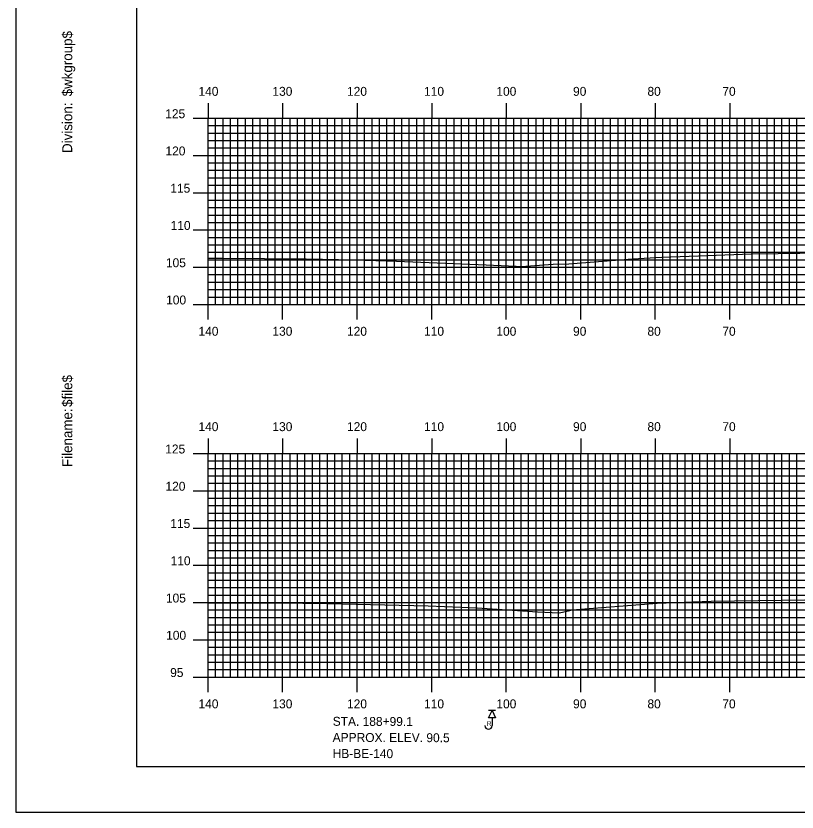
# Model space of a CAD drawing. Extents: x 1788156 to 1788500, y 442591 to 442811.
# Drawn here: x 1788156.3 to 1788261.2, y 442590.5 to 442697.4 of the extents above; entities that cross this region are included whole.
import ezdxf

# ---------------------------------------------------------------- set-up
doc = ezdxf.new("R2010")
doc.units = 0
for name, color, linetype in [('BORDER', 7, 'Continuous'), ('BORING - NO REFUSAL', 7, 'Continuous'), ('BORING - REFUSAL', 7, 'Continuous'), ('H_V ANNOTATION', 7, 'Continuous'), ('MAJOR', 7, 'Continuous'), ('MINOR', 7, 'Continuous'), ('PLOT BOUNDARY', 7, 'Continuous'), ('S_Roadway_Centerline', 7, 'Continuous')]:
    doc.layers.add(name, color=color, linetype=linetype)

msp = doc.modelspace()

# ---------------------------------------------------------------- linework, layer by layer
at = {"layer": 'BORDER'}
msp.add_lwpolyline([(1788172.53, 442596.67), (1788492.53, 442596.67), (1788492.53, 442806.67), (1788172.53, 442806.67)], close=True, dxfattribs=at)
at = {"layer": 'BORING - NO REFUSAL'}
for p, q in [((1788220.71, 442604.17), (1788219.75, 442604.17)), ((1788220.23, 442603.21), (1788220.23, 442602.15))]:
    msp.add_line(p, q, dxfattribs=at)
msp.add_lwpolyline([(1788220.23, 442604.17), (1788220.71, 442603.21), (1788219.75, 442603.21)], close=True, dxfattribs=at)
msp.add_arc((1788219.75, 442602.15), 0.485, 180, 0, dxfattribs=at)
at = {"layer": 'MAJOR'}
for p, q in [((1788182.13, 442685.67), (1788182.13, 442683.67)), ((1788192.13, 442685.67), (1788192.13, 442683.67)), ((1788202.13, 442685.67), (1788202.13, 442683.67)), ((1788212.13, 442685.67), (1788212.13, 442683.67)), ((1788222.13, 442685.67), (1788222.13, 442683.67)), ((1788232.13, 442685.67), (1788232.13, 442683.67)), ((1788242.13, 442685.67), (1788242.13, 442683.67)), ((1788252.13, 442685.67), (1788252.13, 442683.67)), ((1788180.13, 442683.67), (1788182.13, 442683.67)), ((1788182.13, 442683.67), (1788462.13, 442683.67)), ((1788182.13, 442658.67), (1788182.13, 442683.67)), ((1788182.13, 442658.67), (1788182.13, 442683.67)), ((1788182.13, 442683.67), (1788462.13, 442683.67)), ((1788192.13, 442658.67), (1788192.13, 442683.67)), ((1788202.13, 442658.67), (1788202.13, 442683.67)), ((1788212.13, 442658.67), (1788212.13, 442683.67)), ((1788222.13, 442658.67), (1788222.13, 442683.67)), ((1788232.13, 442658.67), (1788232.13, 442683.67)), ((1788242.13, 442658.67), (1788242.13, 442683.67)), ((1788252.13, 442658.67), (1788252.13, 442683.67)), ((1788180.13, 442678.67), (1788182.13, 442678.67)), ((1788182.13, 442678.67), (1788462.13, 442678.67)), ((1788180.13, 442673.67), (1788182.13, 442673.67)), ((1788182.13, 442673.67), (1788462.13, 442673.67)), ((1788180.13, 442668.67), (1788182.13, 442668.67)), ((1788182.13, 442668.67), (1788462.13, 442668.67)), ((1788180.13, 442663.67), (1788182.13, 442663.67)), ((1788182.13, 442663.67), (1788462.13, 442663.67)), ((1788180.13, 442658.67), (1788182.13, 442658.67)), ((1788182.13, 442658.67), (1788462.13, 442658.67)), ((1788182.13, 442658.67), (1788462.13, 442658.67)), ((1788182.13, 442656.66), (1788182.13, 442658.67)), ((1788192.13, 442656.66), (1788192.13, 442658.67)), ((1788202.13, 442656.66), (1788202.13, 442658.67)), ((1788212.13, 442656.66), (1788212.13, 442658.67)), ((1788222.13, 442656.66), (1788222.13, 442658.67)), ((1788232.13, 442656.66), (1788232.13, 442658.67)), ((1788242.13, 442656.66), (1788242.13, 442658.67)), ((1788252.13, 442656.66), (1788252.13, 442658.67)), ((1788182.13, 442640.67), (1788182.13, 442638.67)), ((1788192.13, 442640.67), (1788192.13, 442638.67)), ((1788202.13, 442640.67), (1788202.13, 442638.67)), ((1788212.13, 442640.67), (1788212.13, 442638.67)), ((1788222.13, 442640.67), (1788222.13, 442638.67)), ((1788232.13, 442640.67), (1788232.13, 442638.67)), ((1788242.13, 442640.67), (1788242.13, 442638.67)), ((1788252.13, 442640.67), (1788252.13, 442638.67)), ((1788180.13, 442638.67), (1788182.13, 442638.67)), ((1788182.13, 442638.67), (1788462.13, 442638.67)), ((1788182.13, 442608.67), (1788182.13, 442638.67)), ((1788182.13, 442608.67), (1788182.13, 442638.67)), ((1788182.13, 442638.67), (1788462.13, 442638.67)), ((1788192.13, 442608.67), (1788192.13, 442638.67)), ((1788202.13, 442608.67), (1788202.13, 442638.67)), ((1788212.13, 442608.67), (1788212.13, 442638.67)), ((1788222.13, 442608.67), (1788222.13, 442638.67)), ((1788232.13, 442608.67), (1788232.13, 442638.67)), ((1788242.13, 442608.67), (1788242.13, 442638.67)), ((1788252.13, 442608.67), (1788252.13, 442638.67)), ((1788180.13, 442633.67), (1788182.13, 442633.67)), ((1788182.13, 442633.67), (1788462.13, 442633.67)), ((1788180.13, 442628.67), (1788182.13, 442628.67)), ((1788182.13, 442628.67), (1788462.13, 442628.67)), ((1788180.13, 442623.67), (1788182.13, 442623.67)), ((1788182.13, 442623.67), (1788462.13, 442623.67)), ((1788180.13, 442618.67), (1788182.13, 442618.67)), ((1788182.13, 442618.67), (1788462.13, 442618.67)), ((1788180.13, 442613.67), (1788182.13, 442613.67)), ((1788182.13, 442613.67), (1788462.13, 442613.67)), ((1788180.13, 442608.67), (1788182.13, 442608.67)), ((1788182.13, 442608.67), (1788462.13, 442608.67)), ((1788182.13, 442608.67), (1788462.13, 442608.67)), ((1788182.13, 442606.66), (1788182.13, 442608.67)), ((1788192.13, 442606.66), (1788192.13, 442608.67)), ((1788202.13, 442606.66), (1788202.13, 442608.67)), ((1788212.13, 442606.66), (1788212.13, 442608.67)), ((1788222.13, 442606.66), (1788222.13, 442608.67)), ((1788232.13, 442606.66), (1788232.13, 442608.67)), ((1788242.13, 442606.66), (1788242.13, 442608.67)), ((1788252.13, 442606.66), (1788252.13, 442608.67))]:
    msp.add_line(p, q, dxfattribs=at)
at = {"layer": 'MINOR'}
for p, q in [((1788183.13, 442658.67), (1788183.13, 442683.67)), ((1788184.13, 442658.67), (1788184.13, 442683.67)), ((1788185.13, 442658.67), (1788185.13, 442683.67)), ((1788186.13, 442658.67), (1788186.13, 442683.67)), ((1788187.13, 442658.67), (1788187.13, 442683.67)), ((1788188.13, 442658.67), (1788188.13, 442683.67)), ((1788189.13, 442658.67), (1788189.13, 442683.67)), ((1788190.13, 442658.67), (1788190.13, 442683.67)), ((1788191.13, 442658.67), (1788191.13, 442683.67)), ((1788193.13, 442658.67), (1788193.13, 442683.67)), ((1788194.13, 442658.67), (1788194.13, 442683.67)), ((1788195.13, 442658.67), (1788195.13, 442683.67)), ((1788196.13, 442658.67), (1788196.13, 442683.67)), ((1788197.13, 442658.67), (1788197.13, 442683.67)), ((1788198.13, 442658.67), (1788198.13, 442683.67)), ((1788199.13, 442658.67), (1788199.13, 442683.67)), ((1788200.13, 442658.67), (1788200.13, 442683.67)), ((1788201.13, 442658.67), (1788201.13, 442683.67)), ((1788203.13, 442658.67), (1788203.13, 442683.67)), ((1788204.13, 442658.67), (1788204.13, 442683.67)), ((1788205.13, 442658.67), (1788205.13, 442683.67)), ((1788206.13, 442658.67), (1788206.13, 442683.67)), ((1788207.13, 442658.67), (1788207.13, 442683.67)), ((1788208.13, 442658.67), (1788208.13, 442683.67)), ((1788209.13, 442658.67), (1788209.13, 442683.67)), ((1788210.13, 442658.67), (1788210.13, 442683.67)), ((1788211.13, 442658.67), (1788211.13, 442683.67)), ((1788213.13, 442658.67), (1788213.13, 442683.67)), ((1788214.13, 442658.67), (1788214.13, 442683.67)), ((1788215.13, 442658.67), (1788215.13, 442683.67)), ((1788216.13, 442658.67), (1788216.13, 442683.67)), ((1788217.13, 442658.67), (1788217.13, 442683.67)), ((1788218.13, 442658.67), (1788218.13, 442683.67)), ((1788219.13, 442658.67), (1788219.13, 442683.67)), ((1788220.13, 442658.67), (1788220.13, 442683.67)), ((1788221.13, 442658.67), (1788221.13, 442683.67)), ((1788223.13, 442658.67), (1788223.13, 442683.67)), ((1788224.13, 442658.67), (1788224.13, 442683.67)), ((1788225.13, 442658.67), (1788225.13, 442683.67)), ((1788226.13, 442658.67), (1788226.13, 442683.67)), ((1788227.13, 442658.67), (1788227.13, 442683.67)), ((1788228.13, 442658.67), (1788228.13, 442683.67)), ((1788229.13, 442658.67), (1788229.13, 442683.67)), ((1788230.13, 442658.67), (1788230.13, 442683.67)), ((1788231.13, 442658.67), (1788231.13, 442683.67)), ((1788233.13, 442658.67), (1788233.13, 442683.67)), ((1788234.13, 442658.67), (1788234.13, 442683.67)), ((1788235.13, 442658.67), (1788235.13, 442683.67)), ((1788236.13, 442658.67), (1788236.13, 442683.67)), ((1788237.13, 442658.67), (1788237.13, 442683.67)), ((1788238.13, 442658.67), (1788238.13, 442683.67)), ((1788239.13, 442658.67), (1788239.13, 442683.67)), ((1788240.13, 442658.67), (1788240.13, 442683.67)), ((1788241.13, 442658.67), (1788241.13, 442683.67)), ((1788243.13, 442658.67), (1788243.13, 442683.67)), ((1788244.13, 442658.67), (1788244.13, 442683.67)), ((1788245.13, 442658.67), (1788245.13, 442683.67)), ((1788246.13, 442658.67), (1788246.13, 442683.67)), ((1788247.13, 442658.67), (1788247.13, 442683.67)), ((1788248.13, 442658.67), (1788248.13, 442683.67)), ((1788249.13, 442658.67), (1788249.13, 442683.67)), ((1788250.13, 442658.67), (1788250.13, 442683.67)), ((1788251.13, 442658.67), (1788251.13, 442683.67)), ((1788253.13, 442658.67), (1788253.13, 442683.67)), ((1788254.13, 442658.67), (1788254.13, 442683.67)), ((1788255.13, 442658.67), (1788255.13, 442683.67)), ((1788256.13, 442658.67), (1788256.13, 442683.67)), ((1788257.13, 442658.67), (1788257.13, 442683.67)), ((1788258.13, 442658.67), (1788258.13, 442683.67)), ((1788259.13, 442658.67), (1788259.13, 442683.67)), ((1788260.13, 442658.67), (1788260.13, 442683.67)), ((1788261.13, 442658.67), (1788261.13, 442683.67)), ((1788182.13, 442682.67), (1788462.13, 442682.67)), ((1788182.13, 442682.67), (1788184.13, 442682.67)), ((1788182.13, 442681.67), (1788462.13, 442681.67)), ((1788182.13, 442681.67), (1788184.13, 442681.67)), ((1788182.13, 442680.67), (1788462.13, 442680.67)), ((1788182.13, 442680.67), (1788184.13, 442680.67)), ((1788182.13, 442679.67), (1788462.13, 442679.67)), ((1788182.13, 442679.67), (1788184.13, 442679.67)), ((1788182.13, 442677.67), (1788462.13, 442677.67)), ((1788182.13, 442677.67), (1788184.13, 442677.67)), ((1788182.13, 442676.67), (1788462.13, 442676.67)), ((1788182.13, 442676.67), (1788184.13, 442676.67)), ((1788182.13, 442675.67), (1788462.13, 442675.67)), ((1788182.13, 442675.67), (1788184.13, 442675.67)), ((1788182.13, 442674.67), (1788462.13, 442674.67)), ((1788182.13, 442674.67), (1788184.13, 442674.67)), ((1788182.13, 442672.67), (1788462.13, 442672.67)), ((1788182.13, 442672.67), (1788184.13, 442672.67)), ((1788182.13, 442671.67), (1788462.13, 442671.67)), ((1788182.13, 442671.67), (1788184.13, 442671.67)), ((1788182.13, 442670.67), (1788462.13, 442670.67)), ((1788182.13, 442670.67), (1788184.13, 442670.67)), ((1788182.13, 442669.67), (1788462.13, 442669.67)), ((1788182.13, 442669.67), (1788184.13, 442669.67)), ((1788182.13, 442667.67), (1788462.13, 442667.67)), ((1788182.13, 442667.67), (1788184.13, 442667.67)), ((1788182.13, 442666.67), (1788462.13, 442666.67)), ((1788182.13, 442666.67), (1788184.13, 442666.67)), ((1788182.13, 442665.67), (1788462.13, 442665.67)), ((1788182.13, 442665.67), (1788184.13, 442665.67)), ((1788182.13, 442664.67), (1788462.13, 442664.67)), ((1788182.13, 442664.67), (1788184.13, 442664.67)), ((1788182.13, 442662.67), (1788462.13, 442662.67)), ((1788182.13, 442662.67), (1788184.13, 442662.67)), ((1788182.13, 442661.67), (1788462.13, 442661.67)), ((1788182.13, 442661.67), (1788184.13, 442661.67)), ((1788182.13, 442660.67), (1788462.13, 442660.67)), ((1788182.13, 442660.67), (1788184.13, 442660.67)), ((1788182.13, 442659.67), (1788462.13, 442659.67)), ((1788182.13, 442659.67), (1788184.13, 442659.67)), ((1788183.13, 442608.67), (1788183.13, 442638.67)), ((1788184.13, 442608.67), (1788184.13, 442638.67)), ((1788185.13, 442608.67), (1788185.13, 442638.67)), ((1788186.13, 442608.67), (1788186.13, 442638.67)), ((1788187.13, 442608.67), (1788187.13, 442638.67)), ((1788188.13, 442608.67), (1788188.13, 442638.67)), ((1788189.13, 442608.67), (1788189.13, 442638.67)), ((1788190.13, 442608.67), (1788190.13, 442638.67)), ((1788191.13, 442608.67), (1788191.13, 442638.67)), ((1788193.13, 442608.67), (1788193.13, 442638.67)), ((1788194.13, 442608.67), (1788194.13, 442638.67)), ((1788195.13, 442608.67), (1788195.13, 442638.67)), ((1788196.13, 442608.67), (1788196.13, 442638.67)), ((1788197.13, 442608.67), (1788197.13, 442638.67)), ((1788198.13, 442608.67), (1788198.13, 442638.67)), ((1788199.13, 442608.67), (1788199.13, 442638.67)), ((1788200.13, 442608.67), (1788200.13, 442638.67)), ((1788201.13, 442608.67), (1788201.13, 442638.67)), ((1788203.13, 442608.67), (1788203.13, 442638.67)), ((1788204.13, 442608.67), (1788204.13, 442638.67)), ((1788205.13, 442608.67), (1788205.13, 442638.67)), ((1788206.13, 442608.67), (1788206.13, 442638.67)), ((1788207.13, 442608.67), (1788207.13, 442638.67)), ((1788208.13, 442608.67), (1788208.13, 442638.67)), ((1788209.13, 442608.67), (1788209.13, 442638.67)), ((1788210.13, 442608.67), (1788210.13, 442638.67)), ((1788211.13, 442608.67), (1788211.13, 442638.67)), ((1788213.13, 442608.67), (1788213.13, 442638.67)), ((1788214.13, 442608.67), (1788214.13, 442638.67)), ((1788215.13, 442608.67), (1788215.13, 442638.67)), ((1788216.13, 442608.67), (1788216.13, 442638.67)), ((1788217.13, 442608.67), (1788217.13, 442638.67)), ((1788218.13, 442608.67), (1788218.13, 442638.67)), ((1788219.13, 442608.67), (1788219.13, 442638.67)), ((1788220.13, 442608.67), (1788220.13, 442638.67)), ((1788221.13, 442608.67), (1788221.13, 442638.67)), ((1788223.13, 442608.67), (1788223.13, 442638.67)), ((1788224.13, 442608.67), (1788224.13, 442638.67)), ((1788225.13, 442608.67), (1788225.13, 442638.67)), ((1788226.13, 442608.67), (1788226.13, 442638.67)), ((1788227.13, 442608.67), (1788227.13, 442638.67)), ((1788228.13, 442608.67), (1788228.13, 442638.67)), ((1788229.13, 442608.67), (1788229.13, 442638.67)), ((1788230.13, 442608.67), (1788230.13, 442638.67)), ((1788231.13, 442608.67), (1788231.13, 442638.67)), ((1788233.13, 442608.67), (1788233.13, 442638.67)), ((1788234.13, 442608.67), (1788234.13, 442638.67)), ((1788235.13, 442608.67), (1788235.13, 442638.67)), ((1788236.13, 442608.67), (1788236.13, 442638.67)), ((1788237.13, 442608.67), (1788237.13, 442638.67)), ((1788238.13, 442608.67), (1788238.13, 442638.67)), ((1788239.13, 442608.67), (1788239.13, 442638.67)), ((1788240.13, 442608.67), (1788240.13, 442638.67)), ((1788241.13, 442608.67), (1788241.13, 442638.67)), ((1788243.13, 442608.67), (1788243.13, 442638.67)), ((1788244.13, 442608.67), (1788244.13, 442638.67)), ((1788245.13, 442608.67), (1788245.13, 442638.67)), ((1788246.13, 442608.67), (1788246.13, 442638.67)), ((1788247.13, 442608.67), (1788247.13, 442638.67)), ((1788248.13, 442608.67), (1788248.13, 442638.67)), ((1788249.13, 442608.67), (1788249.13, 442638.67)), ((1788250.13, 442608.67), (1788250.13, 442638.67)), ((1788251.13, 442608.67), (1788251.13, 442638.67)), ((1788253.13, 442608.67), (1788253.13, 442638.67)), ((1788254.13, 442608.67), (1788254.13, 442638.67)), ((1788255.13, 442608.67), (1788255.13, 442638.67)), ((1788256.13, 442608.67), (1788256.13, 442638.67)), ((1788257.13, 442608.67), (1788257.13, 442638.67)), ((1788258.13, 442608.67), (1788258.13, 442638.67)), ((1788259.13, 442608.67), (1788259.13, 442638.67)), ((1788260.13, 442608.67), (1788260.13, 442638.67)), ((1788261.13, 442608.67), (1788261.13, 442638.67)), ((1788182.13, 442637.67), (1788462.13, 442637.67)), ((1788182.13, 442637.67), (1788184.13, 442637.67)), ((1788182.13, 442636.67), (1788462.13, 442636.67)), ((1788182.13, 442636.67), (1788184.13, 442636.67)), ((1788182.13, 442635.67), (1788462.13, 442635.67)), ((1788182.13, 442635.67), (1788184.13, 442635.67)), ((1788182.13, 442634.67), (1788462.13, 442634.67)), ((1788182.13, 442634.67), (1788184.13, 442634.67)), ((1788182.13, 442632.67), (1788462.13, 442632.67)), ((1788182.13, 442632.67), (1788184.13, 442632.67)), ((1788182.13, 442631.67), (1788462.13, 442631.67)), ((1788182.13, 442631.67), (1788184.13, 442631.67)), ((1788182.13, 442630.67), (1788462.13, 442630.67)), ((1788182.13, 442630.67), (1788184.13, 442630.67)), ((1788182.13, 442629.67), (1788462.13, 442629.67)), ((1788182.13, 442629.67), (1788184.13, 442629.67)), ((1788182.13, 442627.67), (1788462.13, 442627.67)), ((1788182.13, 442627.67), (1788184.13, 442627.67)), ((1788182.13, 442626.67), (1788462.13, 442626.67)), ((1788182.13, 442626.67), (1788184.13, 442626.67)), ((1788182.13, 442625.67), (1788462.13, 442625.67)), ((1788182.13, 442625.67), (1788184.13, 442625.67)), ((1788182.13, 442624.67), (1788462.13, 442624.67)), ((1788182.13, 442624.67), (1788184.13, 442624.67)), ((1788182.13, 442622.67), (1788462.13, 442622.67)), ((1788182.13, 442622.67), (1788184.13, 442622.67)), ((1788182.13, 442621.67), (1788462.13, 442621.67)), ((1788182.13, 442621.67), (1788184.13, 442621.67)), ((1788182.13, 442620.67), (1788462.13, 442620.67)), ((1788182.13, 442620.67), (1788184.13, 442620.67)), ((1788182.13, 442619.67), (1788462.13, 442619.67)), ((1788182.13, 442619.67), (1788184.13, 442619.67)), ((1788182.13, 442617.67), (1788462.13, 442617.67)), ((1788182.13, 442617.67), (1788184.13, 442617.67)), ((1788182.13, 442616.67), (1788462.13, 442616.67)), ((1788182.13, 442616.67), (1788184.13, 442616.67)), ((1788182.13, 442615.67), (1788462.13, 442615.67)), ((1788182.13, 442615.67), (1788184.13, 442615.67)), ((1788182.13, 442614.67), (1788462.13, 442614.67)), ((1788182.13, 442614.67), (1788184.13, 442614.67)), ((1788182.13, 442612.67), (1788462.13, 442612.67)), ((1788182.13, 442612.67), (1788184.13, 442612.67)), ((1788182.13, 442611.67), (1788462.13, 442611.67)), ((1788182.13, 442611.67), (1788184.13, 442611.67)), ((1788182.13, 442610.67), (1788462.13, 442610.67)), ((1788182.13, 442610.67), (1788184.13, 442610.67)), ((1788182.13, 442609.67), (1788462.13, 442609.67)), ((1788182.13, 442609.67), (1788184.13, 442609.67))]:
    msp.add_line(p, q, dxfattribs=at)
at = {"layer": 'PLOT BOUNDARY'}
msp.add_lwpolyline([(1788156.34, 442590.55), (1788496.34, 442590.55), (1788496.34, 442810.55), (1788156.34, 442810.55)], close=True, dxfattribs=at)
at = {"layer": 'S_Roadway_Centerline'}
for points in [[(1788182.13, 442664.9), (1788182.68, 442664.9), (1788183.2, 442664.89), (1788184.1, 442664.88), (1788195.3, 442664.8), (1788201.81, 442664.66), (1788207.39, 442664.49), (1788219.46, 442663.98), (1788224.46, 442663.76), (1788224.78, 442663.8), (1788228.42, 442664.08), (1788230.54, 442664.13), (1788239.09, 442664.78), (1788243.03, 442665.01), (1788249.15, 442665.25), (1788255, 442665.47), (1788258.62, 442665.51), (1788267.31, 442665.64)], [(1788182.13, 442618.64), (1788182.53, 442618.65), (1788192.68, 442618.62), (1788194.82, 442618.59), (1788198.1, 442618.52), (1788211.66, 442618.21), (1788218.25, 442617.97), (1788226.35, 442617.44), (1788229.3, 442617.29), (1788230.68, 442617.62), (1788231, 442617.67), (1788242.4, 442618.6), (1788249.62, 442618.84), (1788262.21, 442619.01)]]:
    msp.add_lwpolyline(points, dxfattribs=at)

# ---------------------------------------------------------------- texts
at = {"layer": 'BORDER'}
for s, p in [('$wkgroup$', (1788163.9, 442686.6)), ('Division:', (1788163.9, 442679)), ('$file$', (1788163.9, 442644.92)), ('Filename:', (1788163.9, 442636.86))]:
    msp.add_text(s, height=1.339, rotation=90, dxfattribs=at).set_placement(p)
at = {"layer": 'BORING - NO REFUSAL'}
msp.add_text('R', height=0.64, dxfattribs=at).set_placement((1788219.52, 442602.09))
at = {"layer": 'BORING - REFUSAL'}
for s, p in [('STA. 188+99.1', (1788198.85, 442602.13)), ('APPROX. ELEV. 90.5', (1788198.84, 442599.97)), ('HB-BE-140', (1788198.84, 442597.81))]:
    msp.add_text(s, height=1.2, rotation=359.8142, dxfattribs=at).set_placement(p)
at = {"layer": 'H_V ANNOTATION'}
for s, p in [('140', (1788180.84, 442686.67)), ('130', (1788190.76, 442686.67)), ('120', (1788200.77, 442686.67)), ('110', (1788211.11, 442686.67)), ('100', (1788220.81, 442686.67)), ('90', (1788231.1, 442686.67)), ('80', (1788241.08, 442686.67)), ('70', (1788251.13, 442686.67)), ('125', (1788176.38, 442683.67)), ('120', (1788176.41, 442678.67)), ('115', (1788177.06, 442673.67)), ('110', (1788177.1, 442668.67)), ('105', (1788176.47, 442663.67)), ('100', (1788176.5, 442658.67)), ('140', (1788180.84, 442654.47)), ('130', (1788190.76, 442654.47)), ('120', (1788200.77, 442654.47)), ('110', (1788211.11, 442654.47)), ('100', (1788220.81, 442654.47)), ('90', (1788231.1, 442654.47)), ('80', (1788241.08, 442654.47)), ('70', (1788251.13, 442654.47)), ('140', (1788180.84, 442641.67)), ('130', (1788190.76, 442641.67)), ('120', (1788200.77, 442641.67)), ('110', (1788211.11, 442641.67)), ('100', (1788220.81, 442641.67)), ('90', (1788231.1, 442641.67)), ('80', (1788241.08, 442641.67)), ('70', (1788251.13, 442641.67)), ('125', (1788176.38, 442638.67)), ('120', (1788176.41, 442633.67)), ('115', (1788177.06, 442628.67)), ('110', (1788177.1, 442623.67)), ('105', (1788176.47, 442618.67)), ('100', (1788176.5, 442613.67)), ('95', (1788177.04, 442608.67)), ('140', (1788180.84, 442604.47)), ('130', (1788190.76, 442604.47)), ('120', (1788200.77, 442604.47)), ('110', (1788211.11, 442604.47)), ('100', (1788220.81, 442604.47)), ('90', (1788231.1, 442604.47)), ('80', (1788241.08, 442604.47)), ('70', (1788251.13, 442604.47))]:
    msp.add_text(s, height=1.2, dxfattribs=at).set_placement(p)
at = {"layer": 'MAJOR'}
for p in [(1788182.12, 442658.67), (1788182.12, 442608.67)]:
    msp.add_text('-', height=0.012, dxfattribs=at).set_placement(p)

doc.saveas('drawing.dxf')
